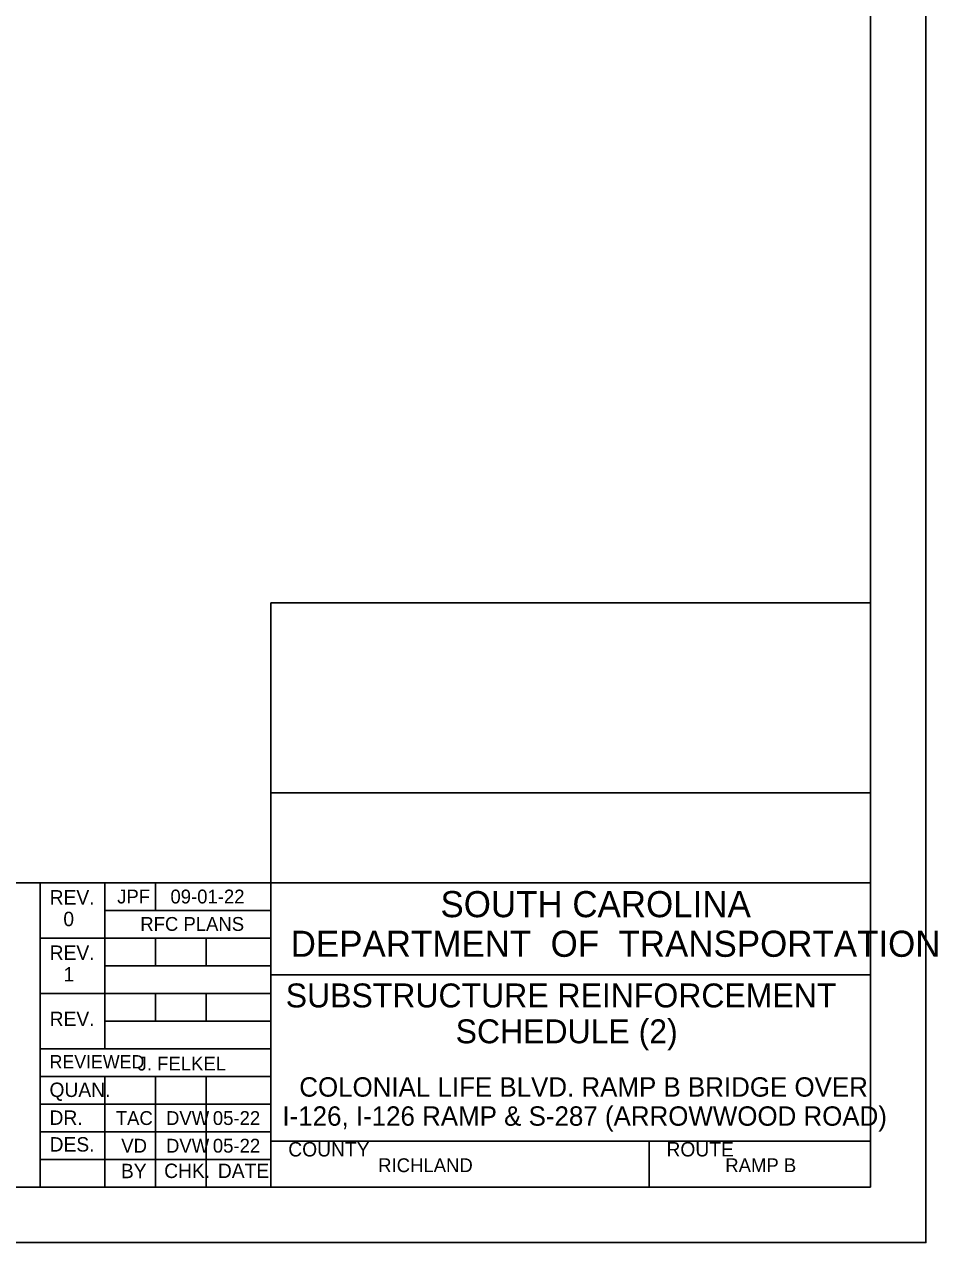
# Model space of a CAD drawing. Extents: x -121.2 to -24.9, y 6.4 to 65.5.
# Drawn here: x -46.88 to -24.88, y 6.35 to 35.68 of the extents above; entities that cross this region are included whole.
import ezdxf

# ---------------------------------------------------------------- set-up
doc = ezdxf.new("R2010")
doc.units = 0
for name, color, linetype in [('BR_BORDER LINES', 7, 'Continuous'), ('BR_TEXT', 7, 'Continuous'), ('Level 31', 7, 'Continuous')]:
    doc.layers.add(name, color=color, linetype=linetype)

msp = doc.modelspace()

# ---------------------------------------------------------------- linework, layer by layer
at = {"layer": 'BR_BORDER LINES'}
for p, q in [((-26.496, 7.683), (-26.496, 63.683)), ((-40.941, 7.683), (-40.941, 21.754)), ((-40.941, 21.754), (-26.496, 21.754)), ((-40.94, 17.182), (-26.496, 17.182)), ((-60.804, 15.017), (-46.496, 15.017)), ((-46.496, 7.683), (-46.496, 15.017)), ((-46.496, 15.017), (-26.496, 15.017)), ((-44.941, 15.017), (-44.941, 11.017)), ((-43.718, 14.35), (-43.718, 15.017)), ((-44.941, 14.35), (-40.941, 14.35)), ((-46.496, 13.684), (-40.941, 13.684)), ((-43.718, 13.017), (-43.718, 13.684)), ((-42.496, 13.017), (-42.496, 13.684)), ((-44.941, 13.017), (-40.941, 13.017)), ((-40.941, 12.795), (-40.941, 12.795)), ((-40.941, 12.795), (-26.495, 12.795)), ((-46.496, 12.35), (-40.941, 12.35)), ((-43.718, 11.684), (-43.718, 12.35)), ((-42.496, 11.684), (-42.496, 12.35)), ((-44.941, 11.684), (-40.941, 11.684)), ((-46.496, 11.017), (-40.941, 11.017)), ((-46.496, 10.35), (-40.941, 10.35)), ((-44.941, 10.35), (-44.941, 7.683)), ((-43.718, 10.35), (-43.718, 7.683)), ((-42.496, 10.35), (-42.496, 7.683)), ((-46.496, 9.683), (-40.941, 9.683)), ((-46.496, 9.017), (-40.941, 9.017)), ((-40.941, 8.795), (-26.496, 8.795)), ((-40.68, 8.795), (-26.496, 8.795)), ((-31.829, 7.683), (-31.829, 8.795)), ((-46.496, 8.35), (-40.941, 8.35)), ((-116.272, 7.683), (-26.496, 7.683))]:
    msp.add_line(p, q, dxfattribs=at)
at = {"layer": 'Level 31'}
msp.add_line((-33.717, 11.621), (-33.717, 11.621), dxfattribs=at)
msp.add_lwpolyline([(-121.161, 6.35), (-25.161, 6.35), (-25.161, 65.017), (-121.161, 65.017)], close=True, dxfattribs=at)

# ---------------------------------------------------------------- texts
at = {"layer": 'BR_TEXT'}
for s, height, p in [('REV.', 0.3467, (-46.27, 14.491)), ('JPF', 0.3333, (-44.643, 14.517)), ('09-01-22', 0.3333, (-43.36, 14.517)), ('SOUTH CAROLINA', 0.62899, (-36.855, 14.186)), ('0', 0.347, (-45.94, 13.971)), ('RFC PLANS', 0.3333, (-44.087, 13.857)), ('DEPARTMENT  OF  TRANSPORTATION', 0.62899, (-40.463, 13.232)), ('REV.', 0.3467, (-46.27, 13.158)), ('1', 0.347, (-45.935, 12.638)), ('SUBSTRUCTURE REINFORCEMENT', 0.576, (-40.583, 12.014)), ('REV.', 0.3467, (-46.27, 11.565)), ('SCHEDULE (2)', 0.576, (-36.489, 11.15)), ('REVIEWED', 0.32, (-46.272, 10.546)), ('J. FELKEL', 0.3333, (-44.152, 10.495)), ('COLONIAL LIFE BLVD. RAMP B BRIDGE OVER', 0.46667, (-40.256, 9.865)), ('QUAN.', 0.3467, (-46.274, 9.857)), ('DR.', 0.3467, (-46.273, 9.186)), ('TAC', 0.3333, (-44.677, 9.183)), ('DVW', 0.3333, (-43.466, 9.183)), ('05-22', 0.3333, (-42.338, 9.183)), ('I-126, I-126 RAMP & S-287 (ARROWWOOD ROAD) ', 0.46667, (-40.662, 9.165)), ('DES.', 0.3467, (-46.271, 8.543)), ('VD', 0.3333, (-44.545, 8.517)), ('DVW', 0.3333, (-43.466, 8.517)), ('05-22', 0.3333, (-42.338, 8.517)), ('COUNTY', 0.3467, (-40.521, 8.425)), ('ROUTE', 0.3467, (-31.41, 8.425)), ('BY', 0.3467, (-44.553, 7.902)), ('CHK.', 0.3467, (-43.511, 7.906)), ('DATE', 0.3467, (-42.217, 7.906)), ('RICHLAND', 0.3333, (-38.355, 8.047)), ('RAMP B', 0.3333, (-29.993, 8.047))]:
    msp.add_text(s, height=height, dxfattribs=at).set_placement(p)

doc.saveas('drawing.dxf')
